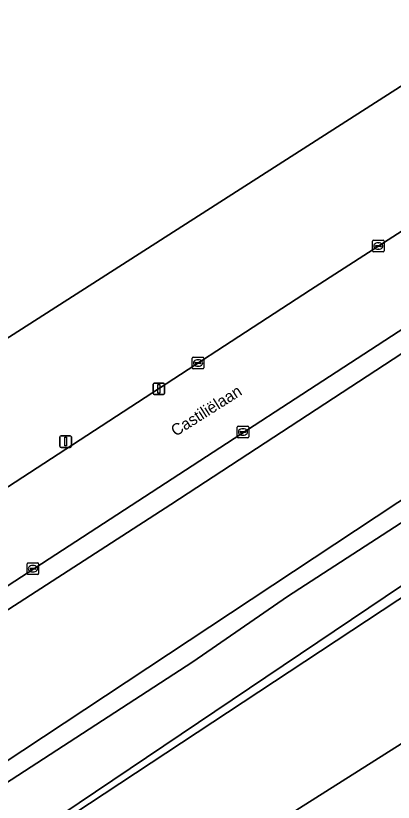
# Model space of a CAD drawing. Extents: x 159451 to 160664, y 388402 to 389723.
# Drawn here: x 159905.3 to 159938, y 389263 to 389331.1 of the extents above; entities that cross this region are included whole.
import ezdxf

# ---------------------------------------------------------------- set-up
doc = ezdxf.new("R2010")
doc.units = 0
for name, color, linetype in [('IMGEO_Berm_groen', 7, 'Continuous'), ('IMGEO_Berm_open', 7, 'Continuous'), ('IMGEO_Erf', 7, 'Continuous'), ('IMGEO_Groenvoorziening', 7, 'Continuous'), ('IMGEO_Kolk', 7, 'Continuous'), ('IMGEO_Lichtmast', 7, 'Continuous'), ('IMGEO_Meer_plas_ven_vijver', 7, 'Continuous'), ('IMGEO_Muur', 7, 'Continuous'), ('IMGEO_Oever', 7, 'Continuous'), ('IMGEO_Openbare_ruimte_label', 7, 'Continuous'), ('IMGEO_Rijbaan_lokaal_gesloten', 7, 'Continuous'), ('IMGEO_Verkeersbordpaal', 7, 'Continuous')]:
    doc.layers.add(name, color=color, linetype=linetype)

msp = doc.modelspace()

# ---------------------------------------------------------------- linework, layer by layer
at = {"layer": 'IMGEO_Berm_groen'}
for points in [[(159986.347, 389343.16), (160000, 389351.609), (160005.853, 389355.231), (160011.539, 389358.226), (160022.23, 389362.941), (160022.748, 389363.161), (160024.313, 389363.825), (160036.109, 389368.424), (160036.171, 389368.928), (160036.044, 389370.934), (160038.034, 389371.101), (160037.552, 389374.642), (160039.622, 389374.924), (160039.49, 389376.111), (160004.126, 389366.97), (159881.386, 389288.321), (159877.675, 389282.045), (159879.112, 389279.636), (159881.68, 389275.33), (159888.243, 389279.608), (159895.867, 389284.578), (159930.803, 389307.353)], [(159994.256, 389325.909), (160002.515, 389330.318), (160007.311, 389333.296), (160003.305, 389339.49), (160002.813, 389340.252), (160000.751, 389338.883), (159999.173, 389341.186), (159962.358, 389317.296), (159918.722, 389288.76), (159890.165, 389270.293), (159890.422, 389265.988), (159893.335, 389261.447), (159891.483, 389260.21), (159891.866, 389259.617), (159900.414, 389263.836)]]:
    msp.add_lwpolyline(points, close=True, dxfattribs=at)
at = {"layer": 'IMGEO_Berm_open'}
msp.add_lwpolyline([(159998.767, 389342.956), (159973.82, 389326.761), (159947.889, 389309.886), (159906.379, 389282.873), (159899.829, 389278.611), (159892.21, 389273.653), (159887.951, 389270.882), (159888.319, 389265.102), (159891.483, 389260.21), (159893.335, 389261.447), (159890.422, 389265.988), (159890.165, 389270.293), (159918.722, 389288.76), (159962.358, 389317.296), (159999.173, 389341.186)], dxfattribs=at)
at = {"layer": 'IMGEO_Erf'}
msp.add_lwpolyline([(159942.266, 389247.926), (159941.93, 389248.418), (159948.152, 389252.517), (159948.928, 389251.327), (159949.376, 389251.62), (159938.655, 389268.003), (159909.424, 389249.498), (159910.724, 389247.444), (159912.114, 389245.249), (159907.059, 389241.966)], dxfattribs=at)
at = {"layer": 'IMGEO_Groenvoorziening'}
for points in [[(159811.911, 389388.896), (159831.103, 389366.948), (159850.684, 389337.235), (159874.344, 389299.539), (159881.386, 389288.321), (160004.126, 389366.97), (160039.49, 389376.111), (160038.576, 389384.307)], [(160006.578, 389323.998), (160004.923, 389322.817), (159998.093, 389318.398), (159982.409, 389309.537), (159903.59, 389257.533), (159904.228, 389257.014), (159904.974, 389257.184), (159905.011, 389256.777), (159904.214, 389256.609), (159903.509, 389257.122), (159903.1, 389257.747), (159896.072, 389253.112), (159898.084, 389250), (159901.295, 389245.033)], [(159905.609, 389244.114), (159910.724, 389247.444), (159909.424, 389249.498), (159938.655, 389268.003), (159939.639, 389268.647), (159954.419, 389278.209), (159953.27, 389279.964), (159964.991, 389287.633), (159995.535, 389307.608)]]:
    msp.add_lwpolyline(points, dxfattribs=at)
at = {"layer": 'IMGEO_Kolk'}
for p, q in [((159936.248, 389311.639), (159937.1, 389311.639)), ((159936.173, 389310.713), (159936.173, 389311.565)), ((159936.432, 389311.133), (159936.432, 389311.145)), ((159936.87, 389311.096), (159936.472, 389311.096)), ((159936.475, 389311.182), (159936.873, 389311.182)), ((159936.661, 389311.419), (159936.686, 389311.419)), ((159936.916, 389311.145), (159936.916, 389311.133)), ((159937.174, 389311.565), (159937.174, 389310.713)), ((159937.1, 389310.639), (159936.248, 389310.639)), ((159936.684, 389310.859), (159936.659, 389310.859)), ((159920.575, 389300.587), (159920.575, 389301.439)), ((159920.65, 389301.513), (159921.502, 389301.513)), ((159921.576, 389301.439), (159921.576, 389300.587)), ((159920.834, 389301.007), (159920.834, 389301.019)), ((159921.272, 389300.97), (159920.874, 389300.97)), ((159920.877, 389301.056), (159921.275, 389301.056)), ((159921.086, 389300.733), (159921.061, 389300.733)), ((159921.063, 389301.293), (159921.088, 389301.293)), ((159921.318, 389301.019), (159921.318, 389301.007)), ((159921.502, 389300.513), (159920.65, 389300.513)), ((159924.462, 389294.611), (159924.462, 389295.463)), ((159924.537, 389295.537), (159925.389, 389295.537)), ((159924.95, 389295.317), (159924.975, 389295.317)), ((159925.463, 389295.463), (159925.463, 389294.611)), ((159924.721, 389295.031), (159924.721, 389295.043)), ((159925.159, 389294.994), (159924.761, 389294.994)), ((159924.764, 389295.08), (159925.162, 389295.08)), ((159924.973, 389294.757), (159924.948, 389294.757)), ((159925.205, 389295.043), (159925.205, 389295.031)), ((159925.389, 389294.537), (159924.537, 389294.537)), ((159906.349, 389283.685), (159907.201, 389283.685)), ((159906.274, 389282.759), (159906.274, 389283.611)), ((159906.533, 389283.179), (159906.533, 389283.191)), ((159906.971, 389283.142), (159906.573, 389283.142)), ((159906.576, 389283.228), (159906.974, 389283.228)), ((159906.762, 389283.465), (159906.787, 389283.465)), ((159907.017, 389283.191), (159907.017, 389283.179)), ((159907.275, 389283.611), (159907.275, 389282.759)), ((159907.201, 389282.685), (159906.349, 389282.685)), ((159906.785, 389282.905), (159906.76, 389282.905))]:
    msp.add_line(p, q, dxfattribs=at)
for points in [[(159936.248, 389311.639), (159937.1, 389311.639)], [(159936.173, 389310.713), (159936.173, 389311.565)], [(159937.174, 389311.565), (159937.174, 389310.713)], [(159937.1, 389310.639), (159936.248, 389310.639)], [(159920.575, 389300.587), (159920.575, 389301.439)], [(159920.65, 389301.513), (159921.502, 389301.513)], [(159921.576, 389301.439), (159921.576, 389300.587)], [(159921.502, 389300.513), (159920.65, 389300.513)], [(159924.462, 389294.611), (159924.462, 389295.463)], [(159924.537, 389295.537), (159925.389, 389295.537)], [(159925.463, 389295.463), (159925.463, 389294.611)], [(159925.389, 389294.537), (159924.537, 389294.537)], [(159906.349, 389283.685), (159907.201, 389283.685)], [(159906.274, 389282.759), (159906.274, 389283.611)], [(159907.275, 389283.611), (159907.275, 389282.759)], [(159907.201, 389282.685), (159906.349, 389282.685)]]:
    msp.add_lwpolyline(points, dxfattribs=at)
for centre, radius, start, end in [((159936.25, 389311.563), 0.0765, 91.55205, 178.44795), ((159936.25, 389311.563), 0.0765, 91.55205, 178.44795), ((159937.098, 389311.563), 0.0765, 1.55205, 88.44795), ((159937.098, 389311.563), 0.0765, 1.55205, 88.44795), ((159936.472, 389311.142), 0.0403, 85.87752, 175.75265), ((159936.469, 389311.132), 0.0366, 178.93798, 274.71019), ((159936.873, 389311.139), 0.043, 264.86636, 352.45326), ((159936.877, 389311.144), 0.0386, 1.73085, 96.63898), ((159936.25, 389310.715), 0.0765, 181.55205, 268.44795), ((159936.25, 389310.715), 0.0765, 181.55205, 268.44795), ((159937.098, 389310.715), 0.0765, 271.55205, 358.44795), ((159937.098, 389310.715), 0.0765, 271.55205, 358.44795), ((159920.652, 389301.437), 0.0765, 91.55205, 178.44795), ((159920.652, 389301.437), 0.0765, 91.55205, 178.44795), ((159921.5, 389301.437), 0.0765, 1.55205, 88.44795), ((159921.5, 389301.437), 0.0765, 1.55205, 88.44795), ((159920.874, 389301.016), 0.0403, 85.87752, 175.75265), ((159920.871, 389301.006), 0.0366, 178.93798, 274.71019), ((159921.275, 389301.013), 0.043, 264.86636, 352.45326), ((159921.279, 389301.018), 0.0386, 1.73085, 96.63898), ((159920.652, 389300.589), 0.0765, 181.55205, 268.44795), ((159920.652, 389300.589), 0.0765, 181.55205, 268.44795), ((159921.5, 389300.589), 0.0765, 271.55205, 358.44795), ((159921.5, 389300.589), 0.0765, 271.55205, 358.44795), ((159924.539, 389295.461), 0.0765, 91.55205, 178.44795), ((159924.539, 389295.461), 0.0765, 91.55205, 178.44795), ((159925.387, 389295.461), 0.0765, 1.55205, 88.44795), ((159925.387, 389295.461), 0.0765, 1.55205, 88.44795), ((159924.539, 389294.613), 0.0765, 181.55205, 268.44795), ((159924.539, 389294.613), 0.0765, 181.55205, 268.44795), ((159924.761, 389295.04), 0.0403, 85.87752, 175.75265), ((159924.758, 389295.03), 0.0366, 178.93798, 274.71019), ((159925.162, 389295.037), 0.043, 264.86636, 352.45326), ((159925.166, 389295.042), 0.0386, 1.73085, 96.63898), ((159925.387, 389294.613), 0.0765, 271.55205, 358.44795), ((159925.387, 389294.613), 0.0765, 271.55205, 358.44795), ((159906.351, 389283.609), 0.0765, 91.55205, 178.44795), ((159906.351, 389283.609), 0.0765, 91.55205, 178.44795), ((159907.199, 389283.609), 0.0765, 1.55205, 88.44795), ((159907.199, 389283.609), 0.0765, 1.55205, 88.44795), ((159906.573, 389283.188), 0.0403, 85.87752, 175.75265), ((159906.57, 389283.178), 0.0366, 178.93798, 274.71019), ((159906.974, 389283.185), 0.043, 264.86636, 352.45326), ((159906.978, 389283.19), 0.0386, 1.73085, 96.63898), ((159906.351, 389282.761), 0.0765, 181.55205, 268.44795), ((159906.351, 389282.761), 0.0765, 181.55205, 268.44795), ((159907.199, 389282.761), 0.0765, 271.55205, 358.44795), ((159907.199, 389282.761), 0.0765, 271.55205, 358.44795)]:
    msp.add_arc(centre, radius, start, end, dxfattribs=at)
for centre, major_axis, ratio, start_param, end_param in [((159936.66, 389311.139), (-0.387, 0.002), 0.722429, 4.712389, 7.853982), ((159936.685, 389311.139), (-0.39, 0.002), 0.717154, 1.570796, 4.712389), ((159921.062, 389301.013), (-0.387, 0.002), 0.722429, 4.712389, 7.853982), ((159921.087, 389301.013), (-0.39, 0.002), 0.717154, 1.570796, 4.712389), ((159924.949, 389295.037), (-0.387, 0.002), 0.722429, 4.712389, 7.853982), ((159924.974, 389295.037), (-0.39, 0.002), 0.717154, 1.570796, 4.712389), ((159906.761, 389283.185), (-0.387, 0.002), 0.722429, 4.712389, 7.853982), ((159906.786, 389283.185), (-0.39, 0.002), 0.717154, 1.570796, 4.712389)]:
    msp.add_ellipse(centre, major_axis=major_axis, ratio=ratio, start_param=start_param, end_param=end_param, dxfattribs=at)
at = {"layer": 'IMGEO_Lichtmast'}
for p, q in [((159917.183, 389298.367), (159917.183, 389299.167)), ((159917.183, 389299.167), (159917.183, 389298.367)), ((159917.283, 389299.267), (159918.073, 389299.267)), ((159918.073, 389299.267), (159917.283, 389299.267)), ((159918.173, 389299.167), (159918.173, 389298.367)), ((159918.173, 389298.367), (159918.173, 389299.167)), ((159918.073, 389298.267), (159917.283, 389298.267)), ((159917.283, 389298.267), (159918.073, 389298.267))]:
    msp.add_line(p, q, dxfattribs=at)
msp.add_lwpolyline([(159917.603, 389299.142), (159917.753, 389299.142), (159917.753, 389298.392), (159917.603, 389298.392), (159917.603, 389299.142)], dxfattribs=at)
for centre, start, end in [((159917.283, 389299.167), 90, 180), ((159917.283, 389299.167), 90, 180), ((159918.073, 389299.167), 0, 90), ((159918.073, 389299.167), 360, 90), ((159917.283, 389298.367), 180, 270), ((159917.283, 389298.367), 180, 270), ((159918.073, 389298.367), 270, 0), ((159918.073, 389298.367), 270, 0)]:
    msp.add_arc(centre, 0.1, start, end, dxfattribs=at)
at = {"layer": 'IMGEO_Meer_plas_ven_vijver'}
msp.add_lwpolyline([(159903.345, 389257.909), (159944.673, 389285.746), (160000, 389321.662), (160003.949, 389324.195), (160004.343, 389324.524), (160004.669, 389324.919), (160004.839, 389325.365), (160004.885, 389325.674), (160004.826, 389326.387), (160004.671, 389326.735), (160004.225, 389327.159), (160003.97, 389327.295), (160003.261, 389327.475), (160002.883, 389327.47), (160002.289, 389327.319), (160001.83, 389327.109), (160001.378, 389326.86), (159981.497, 389314.971), (159962.252, 389302.438), (159947.84, 389293.112), (159928.801, 389280.791), (159920.612, 389275.106), (159902.083, 389263.092)], dxfattribs=at)
at = {"layer": 'IMGEO_Muur'}
msp.add_lwpolyline([(159881.386, 389288.321), (160004.126, 389366.97), (160039.49, 389376.111)], dxfattribs=at)
at = {"layer": 'IMGEO_Oever'}
for points in [[(160002.515, 389330.318), (159994.256, 389325.909), (159900.414, 389263.836), (159900.667, 389263.489), (159902.083, 389263.092), (159920.612, 389275.106), (159928.801, 389280.791), (159947.84, 389293.112), (159962.252, 389302.438), (159981.497, 389314.971), (160001.378, 389326.86)], [(160001.378, 389326.86), (160001.83, 389327.109), (160002.289, 389327.319), (160002.883, 389327.47), (160003.261, 389327.475), (160003.97, 389327.295), (160004.225, 389327.159), (160004.671, 389326.735), (160004.826, 389326.387), (160004.885, 389325.674), (160004.839, 389325.365), (160004.669, 389324.919), (160004.343, 389324.524), (160003.949, 389324.195), (160000, 389321.662), (159944.673, 389285.746), (159903.345, 389257.909), (159903.59, 389257.533), (159982.409, 389309.537), (159998.093, 389318.398), (160004.923, 389322.817), (160006.578, 389323.998), (160007.084, 389324.359)]]:
    msp.add_lwpolyline(points, dxfattribs=at)
at = {"layer": 'IMGEO_Rijbaan_lokaal_gesloten'}
for points in [[(160094.37, 389373.482), (160093.137, 389373.585), (160080.311, 389374.183), (160069.049, 389373.761), (160058.462, 389372.84), (160048, 389370.978), (160046.187, 389370.471), (160036.109, 389368.424), (160024.313, 389363.825), (160022.748, 389363.161), (160022.23, 389362.941), (160011.539, 389358.226), (160005.853, 389355.231), (160000, 389351.609), (159986.347, 389343.16), (159930.803, 389307.353), (159895.867, 389284.578)], [(159899.829, 389278.611), (159906.379, 389282.873), (159947.889, 389309.886), (159973.82, 389326.761), (159998.767, 389342.956), (160007.263, 389348.152), (160010.772, 389350.117), (160016.232, 389352.698), (160018.636, 389353.826), (160032.195, 389359.336), (160040.867, 389362.059), (160043.572, 389362.677), (160052.23, 389364.656), (160053.828, 389365.016), (160061.034, 389366.231), (160068.28, 389366.858), (160078.591, 389367.387), (160084.27, 389367.302), (160089.122, 389367.059), (160096.479, 389366.433)]]:
    msp.add_lwpolyline(points, dxfattribs=at)
at = {"layer": 'IMGEO_Verkeersbordpaal'}
for p, q in [((159909.115, 389293.799), (159909.115, 389294.599)), ((159909.115, 389294.599), (159909.115, 389293.799)), ((159909.215, 389294.699), (159910.005, 389294.699)), ((159910.005, 389294.699), (159909.215, 389294.699)), ((159910.105, 389294.599), (159910.105, 389293.799)), ((159910.105, 389293.799), (159910.105, 389294.599)), ((159910.005, 389293.699), (159909.215, 389293.699)), ((159909.215, 389293.699), (159910.005, 389293.699))]:
    msp.add_line(p, q, dxfattribs=at)
msp.add_lwpolyline([(159909.535, 389294.574), (159909.685, 389294.574), (159909.685, 389293.824), (159909.535, 389293.824), (159909.535, 389294.574)], dxfattribs=at)
for centre, start, end in [((159909.215, 389294.599), 90, 180), ((159909.215, 389294.599), 90, 180), ((159910.005, 389294.599), 0, 90), ((159910.005, 389294.599), 360, 90), ((159909.215, 389293.799), 180, 270), ((159909.215, 389293.799), 180, 270), ((159910.005, 389293.799), 270, 0), ((159910.005, 389293.799), 270, 0)]:
    msp.add_arc(centre, 0.1, start, end, dxfattribs=at)

# ---------------------------------------------------------------- texts
at = {"layer": 'IMGEO_Openbare_ruimte_label'}
msp.add_text('Castiliëlaan', height=1, rotation=32.33938, dxfattribs=at).set_placement((159919.128, 389294.61))

doc.saveas('drawing.dxf')
